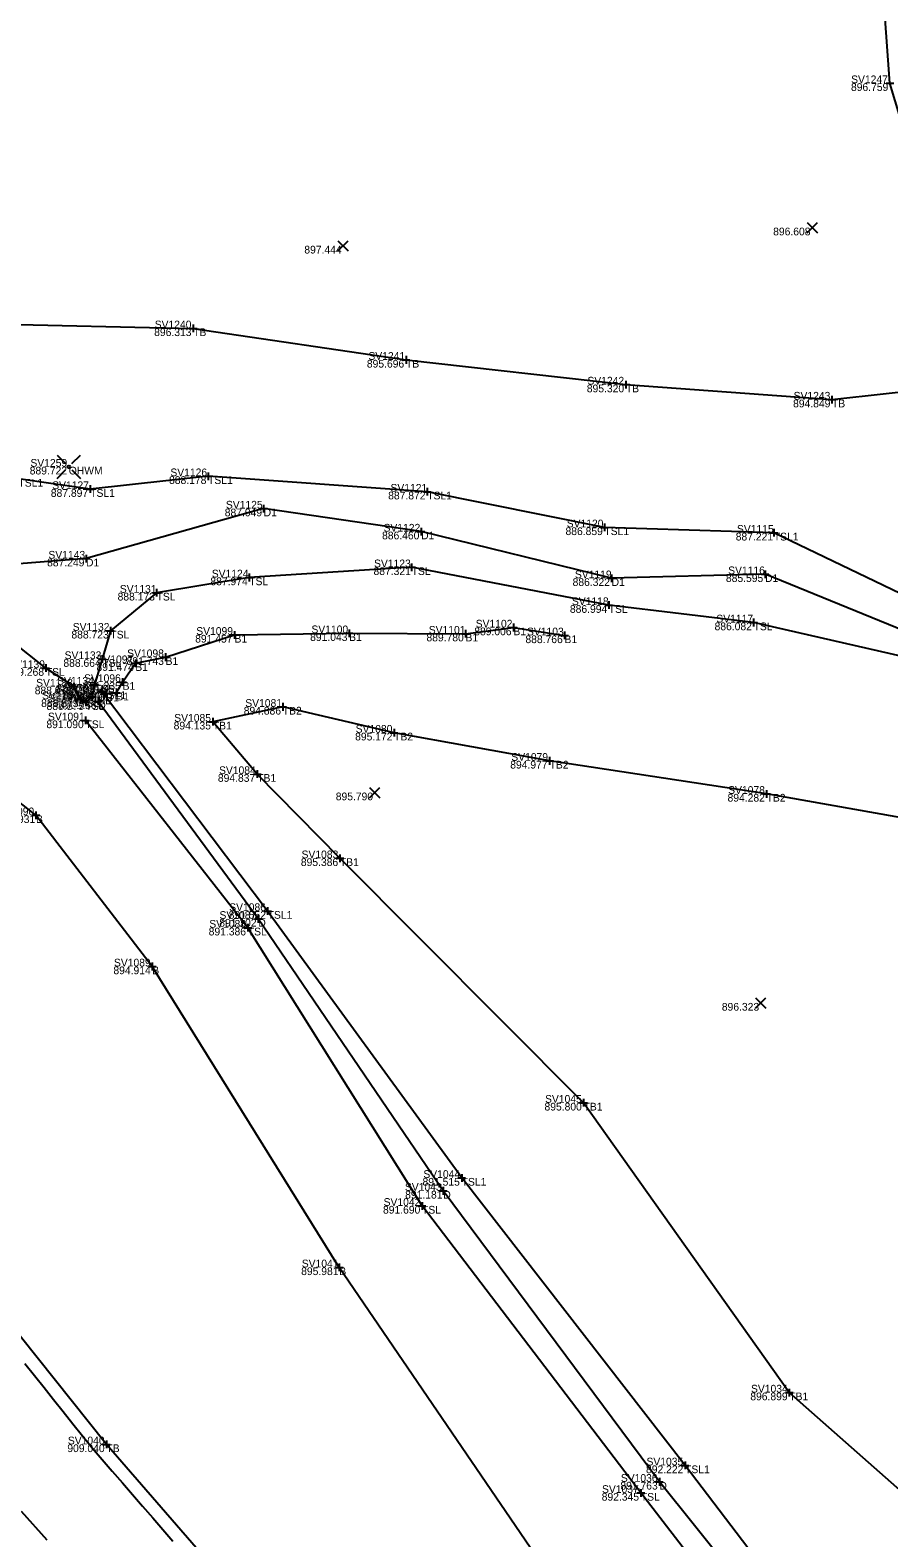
# Model space of a CAD drawing. Extents: x 1918148 to 1919797, y 624701 to 627089.
# Drawn here: x 1919047.5 to 1919158.7, y 625511 to 625706.2 of the extents above; entities that cross this region are included whole.
import ezdxf

# ---------------------------------------------------------------- set-up
doc = ezdxf.new("R2010")
doc.units = 0
for name, color, linetype in [('DR_X_Ditch', 7, 'Continuous'), ('PV_X_Shoulder_Aggregate', 7, 'Continuous'), ('RD_X_Concrete_Pad', 7, 'Continuous'), ('SV_X_Break_Lines', 7, 'Continuous'), ('SV_X_Control_Cells_Found', 7, 'Continuous'), ('SV_X_Random_Point', 7, 'Continuous'), ('SV_X_Shot_Marker', 7, 'Continuous'), ('SV_X_Text_Comment', 7, 'Continuous'), ('SV_X_Text_Elevation', 7, 'Continuous'), ('SV_X_Text_Name', 7, 'Continuous'), ('SV_X_Toe_of_Slope', 7, 'Continuous'), ('SV_X_Top_of_Bank', 7, 'Continuous')]:
    doc.layers.add(name, color=color, linetype=linetype)

msp = doc.modelspace()

# ---------------------------------------------------------------- linework, layer by layer
at = {"layer": 'DR_X_Ditch'}
for points in [[(1919224, 625628.07), (1919215.15, 625628.65), (1919207.75, 625628.36), (1919199.3, 625627.2), (1919183.82, 625625.86), (1919165.06, 625626.67), (1919142.71, 625635.75), (1919122.83, 625635.23), (1919098.16, 625641.27), (1919077.76, 625644.25), (1919054.75, 625637.77), (1919041.67, 625636.77), (1919038.23, 625635.98), (1919036.3, 625636.3), (1919031.6, 625635.22)], [(1919219.02, 625407.66), (1919187.13, 625448.73), (1919151.86, 625489.75), (1919129.02, 625518.23), (1919101.03, 625555.91), (1919077.07, 625591.12), (1919056.34, 625619.29)]]:
    msp.add_lwpolyline(points, dxfattribs=at)
at = {"layer": 'PV_X_Shoulder_Aggregate'}
msp.add_lwpolyline([(1919046.82, 625533.57), (1919048.07, 625532.01), (1919049.32, 625530.44), (1919050.56, 625528.88), (1919051.81, 625527.32), (1919053.06, 625525.75), (1919054.31, 625524.19), (1919055.55, 625522.63), (1919056.84, 625521.1), (1919058.15, 625519.59), (1919059.46, 625518.08), (1919060.77, 625516.57), (1919062.08, 625515.06), (1919063.39, 625513.55), (1919064.7, 625512.04), (1919066.01, 625510.53)], dxfattribs=at)
at = {"layer": 'RD_X_Concrete_Pad'}
msp.add_lwpolyline([(1919046.34, 625514.42), (1919049.69, 625510.71)], dxfattribs=at)
at = {"layer": 'SV_X_Break_Lines'}
for points in [[(1919206.86, 625400.05), (1919170.29, 625439.2), (1919138.05, 625478.01), (1919112.93, 625508.78), (1919087.56, 625546), (1919063.33, 625584.96), (1919048.27, 625604.54), (1919031.79, 625617.49), (1919020.42, 625620.88), (1919013.82, 625627.54), (1919010.2, 625639.42), (1919006.75, 625653.62), (1919000.26, 625672.97)], [(1919057.36, 625620.29), (1919058.68, 625620.41), (1919059.49, 625621.79), (1919061.14, 625624.23), (1919065.06, 625625.01), (1919073.99, 625627.9), (1919088.83, 625628.11), (1919103.91, 625628.05), (1919110.11, 625628.85), (1919116.73, 625627.83)]]:
    msp.add_lwpolyline(points, dxfattribs=at)
at = {"layer": 'SV_X_Control_Cells_Found'}
for p, q in [((1919051.01, 625651.17), (1919052.1, 625650.08)), ((1919052.93, 625650.08), (1919054.03, 625651.17)), ((1919051.01, 625648.16), (1919052.1, 625649.25)), ((1919052.93, 625649.25), (1919054.03, 625648.16))]:
    msp.add_line(p, q, dxfattribs=at)
msp.add_circle((1919052.52, 625649.67), 0.17, dxfattribs=at)
at = {"layer": 'SV_X_Random_Point'}
for p, q in [((1919148.15, 625679.96), (1919149.49, 625681.3)), ((1919148.15, 625681.3), (1919149.49, 625679.96)), ((1919087.39, 625677.61), (1919088.72, 625678.94)), ((1919087.39, 625678.94), (1919088.72, 625677.61)), ((1919091.49, 625606.81), (1919092.83, 625608.15)), ((1919091.49, 625608.15), (1919092.83, 625606.81)), ((1919141.49, 625579.57), (1919142.82, 625580.9)), ((1919141.49, 625580.9), (1919142.82, 625579.57))]:
    msp.add_line(p, q, dxfattribs=at)
at = {"layer": 'SV_X_Shot_Marker'}
for p, q in [((1919158.38, 625699.33), (1919159.38, 625699.33)), ((1919068.13, 625667.59), (1919069.13, 625667.59)), ((1919068.63, 625668.09), (1919068.63, 625667.09)), ((1919068.63, 625667.59), (1919068.63, 625667.59)), ((1919095.7, 625663.51), (1919096.7, 625663.51)), ((1919096.2, 625664.01), (1919096.2, 625663.01)), ((1919096.2, 625663.51), (1919096.2, 625663.51)), ((1919124.18, 625660.31), (1919125.18, 625660.31)), ((1919124.68, 625660.81), (1919124.68, 625659.81)), ((1919124.68, 625660.31), (1919124.68, 625660.31)), ((1919150.88, 625658.36), (1919151.88, 625658.36)), ((1919151.38, 625658.86), (1919151.38, 625657.86)), ((1919151.38, 625658.36), (1919151.38, 625658.36)), ((1919070.06, 625648.44), (1919071.06, 625648.44)), ((1919070.56, 625648.94), (1919070.56, 625647.94)), ((1919070.56, 625648.44), (1919070.56, 625648.44)), ((1919054.79, 625646.77), (1919055.79, 625646.77)), ((1919055.29, 625647.27), (1919055.29, 625646.27)), ((1919055.29, 625646.77), (1919055.29, 625646.77)), ((1919098.45, 625646.44), (1919099.45, 625646.44)), ((1919098.95, 625646.94), (1919098.95, 625645.94)), ((1919098.95, 625646.44), (1919098.95, 625646.44)), ((1919077.26, 625644.25), (1919078.26, 625644.25)), ((1919077.76, 625644.75), (1919077.76, 625643.75)), ((1919077.76, 625644.25), (1919077.76, 625644.25)), ((1919098.16, 625641.77), (1919098.16, 625640.77)), ((1919121.4, 625641.82), (1919122.4, 625641.82)), ((1919121.9, 625642.32), (1919121.9, 625641.32)), ((1919121.9, 625641.82), (1919121.9, 625641.82)), ((1919143.85, 625641.62), (1919143.85, 625640.62)), ((1919097.66, 625641.27), (1919098.66, 625641.27)), ((1919098.16, 625641.27), (1919098.16, 625641.27)), ((1919143.35, 625641.12), (1919144.35, 625641.12)), ((1919143.85, 625641.12), (1919143.85, 625641.12)), ((1919054.25, 625637.77), (1919055.25, 625637.77)), ((1919054.75, 625638.27), (1919054.75, 625637.27)), ((1919054.75, 625637.77), (1919054.75, 625637.77)), ((1919075.89, 625635.83), (1919075.89, 625634.83)), ((1919096.43, 625636.65), (1919097.43, 625636.65)), ((1919096.93, 625637.15), (1919096.93, 625636.15)), ((1919096.93, 625636.65), (1919096.93, 625636.65)), ((1919122.83, 625635.73), (1919122.83, 625634.73)), ((1919142.21, 625635.75), (1919143.21, 625635.75)), ((1919142.71, 625636.25), (1919142.71, 625635.25)), ((1919142.71, 625635.75), (1919142.71, 625635.75)), ((1919063.89, 625633.85), (1919063.89, 625632.85)), ((1919075.39, 625635.33), (1919076.39, 625635.33)), ((1919075.89, 625635.33), (1919075.89, 625635.33)), ((1919122.33, 625635.23), (1919123.33, 625635.23)), ((1919122.83, 625635.23), (1919122.83, 625635.23)), ((1919063.39, 625633.35), (1919064.39, 625633.35)), ((1919063.89, 625633.35), (1919063.89, 625633.35)), ((1919121.96, 625631.75), (1919122.96, 625631.75)), ((1919122.46, 625632.25), (1919122.46, 625631.25)), ((1919122.46, 625631.75), (1919122.46, 625631.75)), ((1919141.22, 625630), (1919141.22, 625629)), ((1919057.41, 625628.43), (1919058.41, 625628.43)), ((1919057.91, 625628.93), (1919057.91, 625627.93)), ((1919057.91, 625628.43), (1919057.91, 625628.43)), ((1919073.49, 625627.9), (1919074.49, 625627.9)), ((1919073.99, 625628.4), (1919073.99, 625627.4)), ((1919073.99, 625627.9), (1919073.99, 625627.9)), ((1919088.33, 625628.11), (1919089.33, 625628.11)), ((1919088.83, 625628.61), (1919088.83, 625627.61)), ((1919088.83, 625628.11), (1919088.83, 625628.11)), ((1919103.41, 625628.05), (1919104.41, 625628.05)), ((1919103.91, 625628.55), (1919103.91, 625627.55)), ((1919103.91, 625628.05), (1919103.91, 625628.05)), ((1919109.61, 625628.85), (1919110.61, 625628.85)), ((1919110.11, 625629.35), (1919110.11, 625628.35)), ((1919110.11, 625628.85), (1919110.11, 625628.85)), ((1919116.23, 625627.83), (1919117.23, 625627.83)), ((1919116.73, 625628.33), (1919116.73, 625627.33)), ((1919116.73, 625627.83), (1919116.73, 625627.83)), ((1919140.72, 625629.5), (1919141.72, 625629.5)), ((1919141.22, 625629.5), (1919141.22, 625629.5)), ((1919049.54, 625624.1), (1919049.54, 625623.1)), ((1919056.35, 625624.76), (1919057.35, 625624.76)), ((1919056.85, 625625.26), (1919056.85, 625624.26)), ((1919056.85, 625624.76), (1919056.85, 625624.76)), ((1919060.64, 625624.23), (1919061.64, 625624.23)), ((1919061.14, 625624.73), (1919061.14, 625623.73)), ((1919061.14, 625624.23), (1919061.14, 625624.23)), ((1919064.56, 625625.01), (1919065.56, 625625.01)), ((1919065.06, 625625.51), (1919065.06, 625624.51)), ((1919065.06, 625625.01), (1919065.06, 625625.01)), ((1919049.04, 625623.6), (1919050.04, 625623.6)), ((1919049.54, 625623.6), (1919049.54, 625623.6)), ((1919055.86, 625621.95), (1919055.86, 625620.95)), ((1919059.49, 625622.29), (1919059.49, 625621.29)), ((1919052.67, 625621.2), (1919053.67, 625621.2)), ((1919053.17, 625621.7), (1919053.17, 625620.7)), ((1919053.17, 625621.2), (1919053.17, 625621.2)), ((1919053.99, 625620.06), (1919053.99, 625619.06)), ((1919055.36, 625621.45), (1919056.36, 625621.45)), ((1919055.54, 625620.41), (1919055.54, 625619.41)), ((1919055.86, 625621.45), (1919055.86, 625621.45)), ((1919056.25, 625620.59), (1919057.25, 625620.59)), ((1919056.75, 625621.09), (1919056.75, 625620.09)), ((1919056.75, 625620.59), (1919056.75, 625620.59)), ((1919056.86, 625620.29), (1919057.86, 625620.29)), ((1919057.36, 625620.79), (1919057.36, 625619.79)), ((1919057.36, 625620.29), (1919057.36, 625620.29)), ((1919058.18, 625620.41), (1919059.18, 625620.41)), ((1919058.68, 625620.91), (1919058.68, 625619.91)), ((1919058.68, 625620.41), (1919058.68, 625620.41)), ((1919058.99, 625621.79), (1919059.99, 625621.79)), ((1919059.49, 625621.79), (1919059.49, 625621.79)), ((1919053.49, 625619.56), (1919054.49, 625619.56)), ((1919053.99, 625619.56), (1919053.99, 625619.56)), ((1919054.21, 625619.18), (1919055.21, 625619.18)), ((1919054.71, 625619.68), (1919054.71, 625618.68)), ((1919054.71, 625619.18), (1919054.71, 625619.18)), ((1919055.04, 625619.91), (1919056.04, 625619.91)), ((1919055.54, 625619.91), (1919055.54, 625619.91)), ((1919055.84, 625619.29), (1919056.84, 625619.29)), ((1919056.34, 625619.79), (1919056.34, 625618.79)), ((1919056.34, 625619.29), (1919056.34, 625619.29)), ((1919079.74, 625618.58), (1919080.74, 625618.58)), ((1919080.24, 625619.08), (1919080.24, 625618.08)), ((1919080.24, 625618.58), (1919080.24, 625618.58)), ((1919054.18, 625616.82), (1919055.18, 625616.82)), ((1919054.68, 625617.32), (1919054.68, 625616.32)), ((1919054.68, 625616.82), (1919054.68, 625616.82)), ((1919070.68, 625616.65), (1919071.68, 625616.65)), ((1919071.18, 625617.15), (1919071.18, 625616.15)), ((1919071.18, 625616.65), (1919071.18, 625616.65)), ((1919094.16, 625615.23), (1919095.16, 625615.23)), ((1919094.66, 625615.73), (1919094.66, 625614.73)), ((1919094.66, 625615.23), (1919094.66, 625615.23)), ((1919076.93, 625610.37), (1919076.93, 625609.37)), ((1919114.3, 625611.59), (1919115.3, 625611.59)), ((1919114.8, 625612.09), (1919114.8, 625611.09)), ((1919114.8, 625611.59), (1919114.8, 625611.59)), ((1919076.43, 625609.87), (1919077.43, 625609.87)), ((1919076.93, 625609.87), (1919076.93, 625609.87)), ((1919142.41, 625607.31), (1919143.41, 625607.31)), ((1919142.91, 625607.81), (1919142.91, 625606.81)), ((1919142.91, 625607.31), (1919142.91, 625607.31)), ((1919047.77, 625604.54), (1919048.77, 625604.54)), ((1919048.27, 625605.04), (1919048.27, 625604.04)), ((1919048.27, 625604.54), (1919048.27, 625604.54)), ((1919087.14, 625598.97), (1919088.14, 625598.97)), ((1919087.64, 625599.47), (1919087.64, 625598.47)), ((1919087.64, 625598.97), (1919087.64, 625598.97)), ((1919076.57, 625591.12), (1919077.57, 625591.12)), ((1919077.07, 625591.62), (1919077.07, 625590.62)), ((1919077.07, 625591.12), (1919077.07, 625591.12)), ((1919077.78, 625592.14), (1919078.78, 625592.14)), ((1919078.28, 625592.64), (1919078.28, 625591.64)), ((1919078.28, 625592.14), (1919078.28, 625592.14)), ((1919075.21, 625589.98), (1919076.21, 625589.98)), ((1919075.71, 625590.48), (1919075.71, 625589.48)), ((1919075.71, 625589.98), (1919075.71, 625589.98)), ((1919062.83, 625584.96), (1919063.83, 625584.96)), ((1919063.33, 625585.46), (1919063.33, 625584.46)), ((1919063.33, 625584.96), (1919063.33, 625584.96)), ((1919118.7, 625567.31), (1919119.7, 625567.31)), ((1919119.2, 625567.81), (1919119.2, 625566.81)), ((1919119.2, 625567.31), (1919119.2, 625567.31)), ((1919102.91, 625557.58), (1919103.91, 625557.58)), ((1919103.41, 625558.08), (1919103.41, 625557.08)), ((1919103.41, 625557.58), (1919103.41, 625557.58)), ((1919100.53, 625555.91), (1919101.53, 625555.91)), ((1919101.03, 625556.41), (1919101.03, 625555.41)), ((1919101.03, 625555.91), (1919101.03, 625555.91)), ((1919097.78, 625553.96), (1919098.78, 625553.96)), ((1919098.28, 625554.46), (1919098.28, 625553.46)), ((1919098.28, 625553.96), (1919098.28, 625553.96)), ((1919087.06, 625546), (1919088.06, 625546)), ((1919087.56, 625546.5), (1919087.56, 625545.5)), ((1919087.56, 625546), (1919087.56, 625546)), ((1919145.85, 625530.29), (1919145.85, 625529.29)), ((1919145.35, 625529.79), (1919146.35, 625529.79)), ((1919145.85, 625529.79), (1919145.85, 625529.79)), ((1919056.89, 625523.08), (1919057.89, 625523.08)), ((1919057.39, 625523.58), (1919057.39, 625522.58)), ((1919057.39, 625523.08), (1919057.39, 625523.08)), ((1919132.35, 625520.85), (1919132.35, 625519.85)), ((1919129.02, 625518.73), (1919129.02, 625517.73)), ((1919131.85, 625520.35), (1919132.85, 625520.35)), ((1919132.35, 625520.35), (1919132.35, 625520.35)), ((1919126.12, 625516.79), (1919127.12, 625516.79)), ((1919126.62, 625517.29), (1919126.62, 625516.29)), ((1919126.62, 625516.79), (1919126.62, 625516.79)), ((1919128.52, 625518.23), (1919129.52, 625518.23)), ((1919129.02, 625518.23), (1919129.02, 625518.23))]:
    msp.add_line(p, q, dxfattribs=at)
at = {"layer": 'SV_X_Toe_of_Slope'}
for points in [[(1919201.2, 625630.95), (1919184.19, 625629.74), (1919164.63, 625631.14), (1919143.85, 625641.12), (1919121.9, 625641.82), (1919098.95, 625646.44), (1919070.56, 625648.44), (1919055.29, 625646.77), (1919046, 625648.09), (1919040.48, 625646.87), (1919038.11, 625645.62)], [(1919201.69, 625623.47), (1919183.29, 625622.3), (1919164.81, 625624.12), (1919141.22, 625629.5), (1919122.46, 625631.75), (1919096.93, 625636.65), (1919075.89, 625635.33), (1919063.89, 625633.35), (1919057.91, 625628.43), (1919056.85, 625624.76), (1919055.86, 625621.45), (1919055.54, 625619.91), (1919054.71, 625619.18), (1919053.99, 625619.56), (1919053.17, 625621.2), (1919049.54, 625623.6), (1919045.1, 625627.13), (1919039.1, 625629.63), (1919034.53, 625630.73)], [(1919222.3, 625409.72), (1919190.71, 625451.22), (1919154.52, 625491.26), (1919132.35, 625520.35), (1919103.41, 625557.58), (1919078.28, 625592.14), (1919056.75, 625620.59)], [(1919214.66, 625404.51), (1919183.35, 625445.99), (1919149.18, 625487.49), (1919126.62, 625516.79), (1919098.28, 625553.96), (1919075.71, 625589.98), (1919054.68, 625616.82)]]:
    msp.add_lwpolyline(points, dxfattribs=at)
at = {"layer": 'SV_X_Top_of_Bank'}
for points in [[(1919180.03, 625377.77), (1919142.39, 625420.85), (1919113.9, 625458.17), (1919086.6, 625489.42), (1919057.39, 625523.08), (1919019.76, 625570.22), (1918998.07, 625602.27), (1918985.26, 625627.56), (1918968.39, 625668.03), (1918955.62, 625707.63), (1918947.9, 625739.17), (1918945.04, 625765.59), (1918947.37, 625785.94), (1918957.93, 625802.75), (1918975.61, 625809.21), (1918997.58, 625813.39), (1919030.67, 625814.44), (1919065.45, 625812.35), (1919111.29, 625808.54)], [(1919008.68, 625701.6), (1919017.73, 625687.93), (1919021.83, 625676.64), (1919027.22, 625671.33), (1919042.19, 625668.18), (1919068.63, 625667.59), (1919096.2, 625663.51), (1919124.68, 625660.31), (1919151.38, 625658.36), (1919165.45, 625659.92), (1919167.97, 625668.32), (1919163.99, 625682.32), (1919158.88, 625699.33), (1919157.69, 625715.48), (1919158.89, 625735.48)], [(1919176.48, 625601.38), (1919142.91, 625607.31), (1919114.8, 625611.59), (1919094.66, 625615.23), (1919080.24, 625618.58), (1919071.18, 625616.65)], [(1919245.91, 625426.64), (1919208.31, 625461.89), (1919173.74, 625505.2), (1919145.85, 625529.79), (1919119.2, 625567.31), (1919087.64, 625598.97), (1919076.93, 625609.87), (1919071.18, 625616.65)]]:
    msp.add_lwpolyline(points, dxfattribs=at)

# ---------------------------------------------------------------- texts
at = {"layer": 'SV_X_Text_Comment'}
for s, p in [('TB', (1919068.63, 625666.59)), ('TB', (1919096.2, 625662.51)), ('TB', (1919124.68, 625659.31)), ('TB', (1919151.38, 625657.36)), ('OHWM', (1919052.52, 625648.67)), ('TSL1', (1919046, 625647.09)), ('TSL1', (1919070.56, 625647.44)), ('TSL1', (1919055.29, 625645.77)), ('TSL1', (1919098.95, 625645.44)), ('D1', (1919077.76, 625643.25)), ('TSL1', (1919121.9, 625640.82)), ('D1', (1919098.16, 625640.27)), ('TSL1', (1919143.85, 625640.12)), ('D1', (1919054.75, 625636.77)), ('TSL', (1919096.93, 625635.65)), ('D1', (1919142.71, 625634.75)), ('TSL', (1919075.89, 625634.33)), ('D1', (1919122.83, 625634.23)), ('TSL', (1919063.89, 625632.35)), ('TSL', (1919122.46, 625630.75)), ('TSL', (1919057.91, 625627.43)), ('B1', (1919073.99, 625626.9)), ('B1', (1919088.83, 625627.11)), ('B1', (1919103.91, 625627.06)), ('B1', (1919110.11, 625627.85)), ('B1', (1919116.73, 625626.83)), ('TSL', (1919141.22, 625628.5)), ('TSL', (1919056.85, 625623.76)), ('B1', (1919061.14, 625623.23)), ('B1', (1919065.06, 625624.01)), ('TSL', (1919049.54, 625622.6)), ('TSL', (1919053.17, 625620.2)), ('TSL', (1919055.86, 625620.45)), ('TSL1', (1919056.75, 625619.59)), ('B1', (1919057.36, 625619.29)), ('B1', (1919058.68, 625619.41)), ('B1', (1919059.49, 625620.79)), ('TSL', (1919053.99, 625618.56)), ('TSL', (1919054.71, 625618.18)), ('TSL', (1919055.54, 625618.91)), ('D', (1919056.34, 625618.29)), ('TB2', (1919080.24, 625617.58)), ('TSL', (1919054.68, 625615.82)), ('TB1', (1919071.18, 625615.65)), ('TB2', (1919094.66, 625614.23)), ('TB2', (1919114.8, 625610.59)), ('TB1', (1919076.93, 625608.87)), ('TB2', (1919142.91, 625606.31)), ('B', (1919048.27, 625603.54)), ('TB1', (1919087.64, 625597.97)), ('D', (1919077.07, 625590.12)), ('TSL1', (1919078.28, 625591.14)), ('TSL', (1919075.71, 625588.98)), ('B', (1919063.33, 625583.96)), ('TB1', (1919119.2, 625566.31)), ('TSL1', (1919103.41, 625556.58)), ('D', (1919101.03, 625554.91)), ('TSL', (1919098.28, 625552.96)), ('B', (1919087.56, 625545)), ('TB1', (1919145.85, 625528.79)), ('TB', (1919057.39, 625522.08)), ('TSL1', (1919132.35, 625519.35)), ('TSL', (1919126.62, 625515.79)), ('D', (1919129.02, 625517.23))]:
    msp.add_text(s, height=1, dxfattribs=at).set_placement(p)
at = {"layer": 'SV_X_Text_Elevation'}
for s, p in [('896.759', (1919153.84, 625698.33)), ('896.608', (1919143.76, 625679.63)), ('897.444', (1919083.03, 625677.28)), ('896.313', (1919063.58, 625666.59)), ('895.696', (1919091.13, 625662.51)), ('895.320', (1919119.62, 625659.31)), ('894.849', (1919146.34, 625657.36)), ('889.722', (1919047.46, 625648.67)), ('888.178', (1919065.51, 625647.44)), ('887.897', (1919050.19, 625645.77)), ('887.872', (1919093.89, 625645.44)), ('887.049', (1919072.72, 625643.25)), ('886.859', (1919116.86, 625640.82)), ('886.460', (1919093.1, 625640.27)), ('887.221', (1919138.91, 625640.12)), ('887.249', (1919049.71, 625636.77)), ('887.321', (1919091.99, 625635.65)), ('885.595', (1919137.64, 625634.75)), ('887.974', (1919070.86, 625634.33)), ('886.322', (1919117.78, 625634.23)), ('888.173', (1919058.84, 625632.35)), ('886.994', (1919117.43, 625630.75)), ('888.723', (1919052.86, 625627.43)), ('891.457', (1919068.89, 625626.9)), ('891.043', (1919083.78, 625627.11)), ('889.780', (1919098.85, 625627.06)), ('889.006', (1919105.04, 625627.85)), ('888.766', (1919111.67, 625626.83)), ('886.082', (1919136.17, 625628.5)), ('888.664', (1919051.82, 625623.76)), ('891.474', (1919056.11, 625623.23)), ('891.743', (1919060.01, 625624.01)), ('889.268', (1919044.48, 625622.6)), ('888.978', (1919048.11, 625620.2)), ('888.761', (1919050.92, 625620.45)), ('890.384', (1919051.72, 625619.59)), ('890.610', (1919052.3, 625619.29)), ('890.957', (1919053.57, 625619.41)), ('891.235', (1919054.42, 625620.79)), ('888.873', (1919048.94, 625618.56)), ('888.875', (1919049.64, 625618.18)), ('888.828', (1919050.48, 625618.91)), ('890.256', (1919051.28, 625618.29)), ('894.886', (1919075.18, 625617.58)), ('891.090', (1919049.62, 625615.82)), ('894.135', (1919066.1, 625615.65)), ('895.172', (1919089.61, 625614.23)), ('894.977', (1919109.7, 625610.59)), ('894.837', (1919071.83, 625608.87)), ('895.790', (1919087.1, 625606.48)), ('894.282', (1919137.85, 625606.31)), ('894.931', (1919043.33, 625603.54)), ('895.386', (1919082.58, 625597.97)), ('891.102', (1919072.01, 625590.12)), ('891.552', (1919073.23, 625591.14)), ('891.386', (1919070.64, 625588.98)), ('894.914', (1919058.3, 625583.96)), ('896.323', (1919137.11, 625579.24)), ('895.800', (1919114.14, 625566.31)), ('891.515', (1919098.34, 625556.58)), ('891.181', (1919096.09, 625554.91)), ('891.690', (1919093.22, 625552.96)), ('895.981', (1919082.62, 625545)), ('896.899', (1919140.8, 625528.79)), ('909.040', (1919052.33, 625522.08)), ('892.222', (1919127.29, 625519.35)), ('892.345', (1919121.55, 625515.79)), ('891.763', (1919123.97, 625517.23))]:
    msp.add_text(s, height=1, dxfattribs=at).set_placement(p)
at = {"layer": 'SV_X_Text_Name'}
for s, p in [('SV1247', (1919153.86, 625699.33)), ('SV1240', (1919063.65, 625667.59)), ('SV1241', (1919091.33, 625663.51)), ('SV1242', (1919119.7, 625660.31)), ('SV1243', (1919146.41, 625658.36)), ('SV1259', (1919047.55, 625649.67)), ('SV1126', (1919065.68, 625648.44)), ('SV1127', (1919050.37, 625646.77)), ('SV1121', (1919094.19, 625646.44)), ('SV1125', (1919072.87, 625644.25)), ('SV1122', (1919093.29, 625641.27)), ('SV1120', (1919117.02, 625641.82)), ('SV1115', (1919139.07, 625641.12)), ('SV1143', (1919049.88, 625637.77)), ('SV1123', (1919092.06, 625636.65)), ('SV1124', (1919071.04, 625635.33)), ('SV1119', (1919118.08, 625635.23)), ('SV1116', (1919137.93, 625635.75)), ('SV1131', (1919059.13, 625633.35)), ('SV1118', (1919117.69, 625631.75)), ('SV1102', (1919105.23, 625628.85)), ('SV1117', (1919136.4, 625629.5)), ('SV1132', (1919053.03, 625628.43)), ('SV1099', (1919069.03, 625627.9)), ('SV1100', (1919083.95, 625628.11)), ('SV1101', (1919099.15, 625628.05)), ('SV1103', (1919111.87, 625627.83)), ('SV1098', (1919060.08, 625625.01)), ('SV1139', (1919044.68, 625623.6)), ('SV1133', (1919051.98, 625624.76)), ('SV1097', (1919056.11, 625624.23)), ('SV1138', (1919048.29, 625621.2)), ('SV1134', (1919051.01, 625621.45)), ('SV1096', (1919054.5, 625621.79)), ('SV1137', (1919049.07, 625619.56)), ('SV1136', (1919049.83, 625619.18)), ('SV1135', (1919050.65, 625619.91)), ('SV1092', (1919051.36, 625619.29)), ('SV1093', (1919051.78, 625620.59)), ('SV1094', (1919052.4, 625620.29)), ('SV1095', (1919053.68, 625620.41)), ('SV1081', (1919075.38, 625618.58)), ('SV1091', (1919049.82, 625616.82)), ('SV1085', (1919066.18, 625616.65)), ('SV1080', (1919089.68, 625615.23)), ('SV1079', (1919109.84, 625611.59)), ('SV1084', (1919071.98, 625609.87)), ('SV1078', (1919137.93, 625607.31)), ('SV1090', (1919043.28, 625604.54)), ('SV1083', (1919082.67, 625598.97)), ('SV1086', (1919073.3, 625592.14)), ('SV1088', (1919070.72, 625589.98)), ('SV1087', (1919072.04, 625591.12)), ('SV1089', (1919058.37, 625584.96)), ('SV1045', (1919114.21, 625567.31)), ('SV1044', (1919098.45, 625557.58)), ('SV1043', (1919096.06, 625555.91)), ('SV1042', (1919093.3, 625553.96)), ('SV1041', (1919082.7, 625546)), ('SV1034', (1919140.89, 625529.79)), ('SV1040', (1919052.4, 625523.08)), ('SV1035', (1919127.35, 625520.35)), ('SV1036', (1919124.03, 625518.23)), ('SV1037', (1919121.59, 625516.79))]:
    msp.add_text(s, height=1, dxfattribs=at).set_placement(p)

doc.saveas('drawing.dxf')
